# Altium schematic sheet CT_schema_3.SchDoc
size 421 x 351 mm
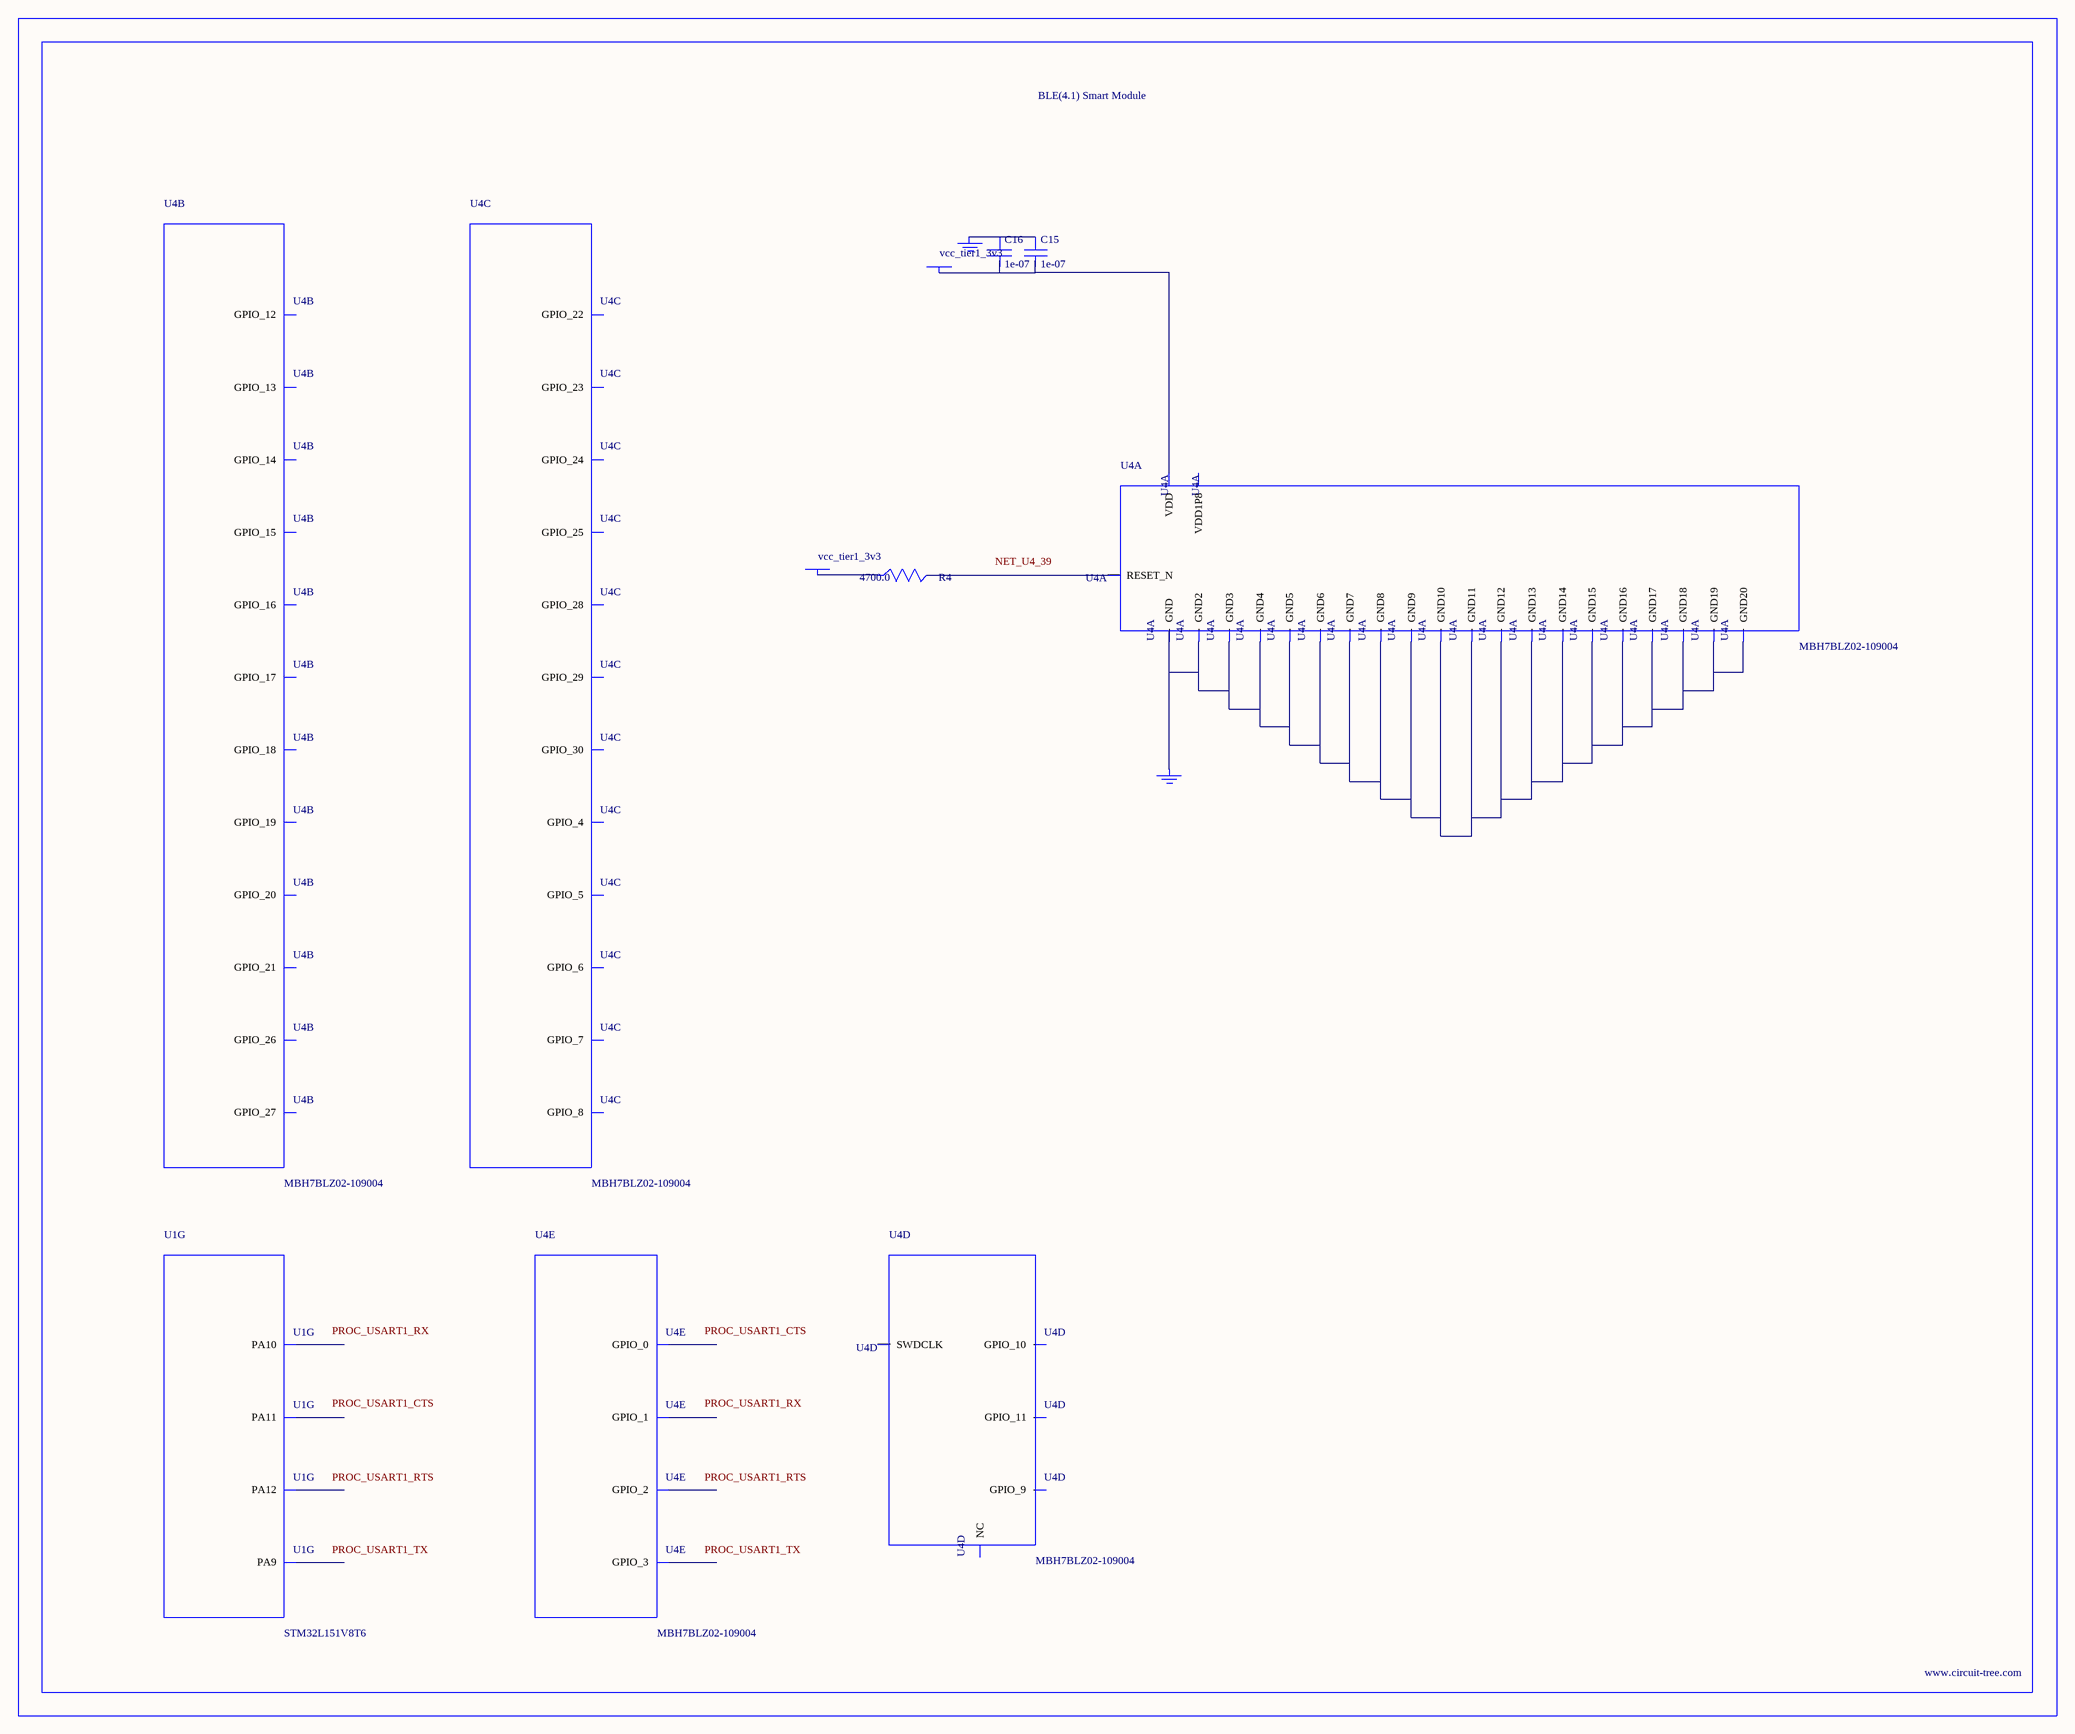
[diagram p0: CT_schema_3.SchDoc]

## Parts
BORDER2  (no value)
C15  1e-07  [C0402]
C16  1e-07  [C0402]
GND_INSTANCE_2_0  (no value)
GND_INSTANCE_2_1  (no value)
POWER_INSTANCE_2_0  vcc_tier1_3v3
POWER_INSTANCE_2_1  vcc_tier1_3v3
R4  4700.0  [R0603]
U1  STM32L151V8T6  [LQFP100]  (part G of 7)
U4  MBH7BLZ02-109004  [MBH7BLZ02-109004]  (parts A,B,C,D,E of 5)

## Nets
NetC15_1: C15.1 C16.1 GND_INSTANCE_2_0.0(GND)
NetC15_2: C15.2 C16.2 POWER_INSTANCE_2_0.0(PWR) U4.28(VDD)
NetGND_INSTANCE_2_1_0: GND_INSTANCE_2_1.0(GND) U4.1(GND) U4.3(GND2) U4.15(GND3) U4.27(GND4) U4.29(GND5) U4.41(GND6) U4.42(GND7) U4.43(GND8) U4.44(GND9) U4.45(GND10) U4.46(GND11) U4.47(GND12) U4.48(GND13) U4.49(GND14) U4.50(GND15) U4.52(GND16) U4.53(GND17) U4.54(GND18) U4.55(GND19) U4.56(GND20)
NetPOWER_INSTANCE_2_1_0: POWER_INSTANCE_2_1.0(PWR) R4.1
NetR4_2: R4.2 U4.39(RESET_N)

Not connected (* = marked no-connect by the designer): U1 68(PA9) 69(PA10) 70(PA11) 71(PA12); U4 2(VDD1P8) 4(GPIO_17) 5(GPIO_19) 6(GPIO_18) 7(GPIO_20) 8(GPIO_16) 9(GPIO_15) 10(GPIO_14) 11(GPIO_13) 12(GPIO_12) 13(GPIO_27) 14(GPIO_26) 16(GPIO_21) 17(GPIO_22) 18(GPIO_23) 19(GPIO_24) 20(GPIO_6) 21(GPIO_5) 22(GPIO_4) 23(GPIO_3) 24(GPIO_2) 25(GPIO_1) 26(GPIO_0) 30(GPIO_25) 31(GPIO_29) 32(GPIO_28) 33(GPIO_30) 34(GPIO_7) 35(GPIO_8) 36(GPIO_9) 37(GPIO_10) 38(GPIO_11) 40(SWDCLK) 51(NC)

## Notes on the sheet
- Labels drawn without touching a wire or pin: NET_U4_39, PROC_USART1_CTS, PROC_USART1_RTS, PROC_USART1_RX, PROC_USART1_TX

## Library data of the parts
BORDER2 = BORDER_PAGE2
C15 C16 = C0402C104K3RACTU
GND_INSTANCE_2_0 GND_INSTANCE_2_1 = GND
POWER_INSTANCE_2_0 POWER_INSTANCE_2_1 = PWR
R4 = RC0603JR-074K7L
